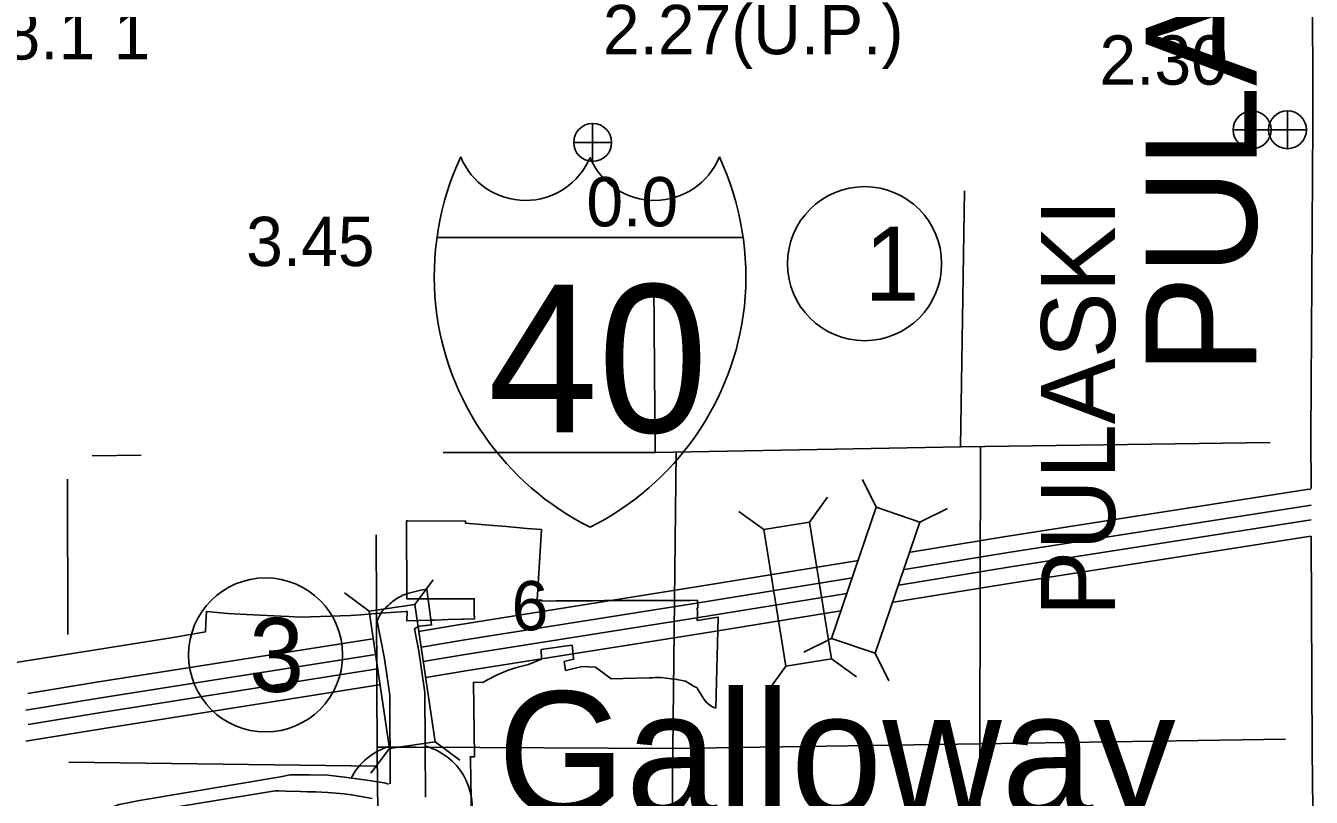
# Model space of a CAD drawing. Extents: x 1127717 to 1741049, y 2026793 to 2244711.
# Drawn here: x 1242222 to 1247728, y 2137280 to 2140586 of the extents above; entities that cross this region are included whole.
import ezdxf

# ---------------------------------------------------------------- set-up
doc = ezdxf.new("R2010")
doc.units = 0
for name, color, linetype in [('10', 7, 'Continuous'), ('15', 7, 'Continuous'), ('19', 7, 'Continuous'), ('2', 7, 'Continuous'), ('20', 7, 'Continuous'), ('23', 7, 'Continuous'), ('24', 7, 'Continuous'), ('25', 7, 'Continuous'), ('26', 7, 'Continuous'), ('27', 7, 'Continuous'), ('30', 7, 'Continuous'), ('4', 7, 'Continuous'), ('5', 7, 'Continuous'), ('58', 7, 'Continuous'), ('6', 7, 'Continuous'), ('Level 30', 7, 'Continuous')]:
    doc.layers.add(name, color=color, linetype=linetype)

msp = doc.modelspace()

# ---------------------------------------------------------------- linework, layer by layer
at = {"layer": '10'}
for points in [[(1243727.1, 2138034.7), (1243730.7, 2138045.4), (1243738.7, 2138060.7), (1243749.6, 2138078.1), (1243759, 2138086.8), (1243764.1, 2138092.6), (1243773.7, 2138101.5), (1243781.3, 2138108.6), (1243786.8, 2138113.3), (1243791.4, 2138117.2), (1243798.7, 2138122.8), (1243806, 2138128), (1243813.3, 2138132.7), (1243821.6, 2138137.6), (1243829.5, 2138141.8), (1243837.4, 2138145.6), (1243845.7, 2138149.1), (1243854.2, 2138152.3), (1243862.8, 2138155.1), (1243914.6, 2138167.8), (1243940.3, 2138171.7), (1243959.9, 2138018.1)], [(1243727.1, 2138034.7), (1243757.5, 2137881.1), (1243767.1, 2137816.1), (1243781.2, 2137717.9)], [(1243886.4, 2138002.3), (1243893.7, 2138006.5), (1243896, 2138007.8), (1243898.4, 2138008.9), (1243900.8, 2138009.9), (1243903.2, 2138010.8), (1243905.7, 2138011.7), (1243908.2, 2138012.4), (1243910.2, 2138012.8), (1243933.1, 2138015.7), (1243936.3, 2138016), (1243959.9, 2138018.1), (1243937.5, 2138016.2), (1243936.7, 2138016.2)], [(1243886.4, 2138002.3), (1243905.4, 2137906.6), (1243915.5, 2137837.7), (1243931.1, 2137729)], [(1243781.2, 2137717.9), (1243783.5, 2137337.7)], [(1243931.1, 2137729), (1243933.8, 2137280.4)]]:
    msp.add_lwpolyline(points, dxfattribs=at)
at = {"layer": '15'}
msp.add_lwpolyline([(1242228.1, 2137005.3), (1242288.1, 2137037.9), (1242295.6, 2137043.4), (1242309.9, 2137054.3), (1242340.9, 2137080.9), (1242411, 2137142.8), (1242436.4, 2137161.8), (1242474, 2137185.2), (1242527.7, 2137209.9), (1242585.3, 2137234.9), (1242622.7, 2137249.3), (1242665.9, 2137258.2), (1242709.8, 2137265.5), (1243312.7, 2137368.1), (1243354.8, 2137376), (1243395.8, 2137376.8), (1243435.9, 2137376.7), (1243515.2, 2137374.8), (1243587.7, 2137366.3), (1243682.5, 2137353), (1243757.1, 2137342.3), (1243777.3, 2137336.7)], dxfattribs=at)
at = {"layer": '19'}
for points in [[(1246011.7, 2138330.4), (1246410.4, 2138395.2), (1247709, 2138598), (1247726.3, 2138600.4)], [(1245985.6, 2138256.5), (1246421.2, 2138327.3), (1247719.1, 2138530), (1247727.6, 2138531.2)], [(1245961.5, 2138189.2), (1246431, 2138265.6), (1247727.6, 2138468.1)], [(1245938.1, 2138115.8), (1246441.8, 2138197.7), (1247726.3, 2138398.3)], [(1244083.4, 2138020.9), (1245084.2, 2138179.6), (1245788.3, 2138294)], [(1244094.2, 2137953), (1245095.1, 2138111.7), (1245762.1, 2138220.1)], [(1244104, 2137891.3), (1245105, 2138050), (1245738.9, 2138153.1)], [(1244114.8, 2137823.4), (1245115.9, 2137982.1), (1245713.5, 2138079.3)], [(1243904.1, 2137990.9), (1244082.6, 2138020.7)], [(1242230.5, 2137724.2), (1242524.5, 2137772.5), (1243708.2, 2137959.4)], [(1243917.2, 2137923.4), (1244094, 2137952.9)], [(1242222.2, 2137653.2), (1242535.4, 2137704.6), (1243719.5, 2137891.5)], [(1243924.5, 2137861.3), (1244104.3, 2137891.3)], [(1242232.3, 2137591.5), (1242545.4, 2137642.9), (1243728, 2137829.6)], [(1243934.9, 2137793.3), (1244115.6, 2137823.5)], [(1242222.5, 2137520.2), (1242556.3, 2137575), (1243735.5, 2137761.2)]]:
    msp.add_lwpolyline(points, dxfattribs=at)
at = {"layer": '2'}
for points in [[(1247663.1, 2144020.7), (1247662.8, 2142760.5), (1247726.6, 2142761.9), (1247731.3, 2141494.2), (1247734.4, 2140166.2), (1247725.8, 2138824.4), (1247726.7, 2138603.6)], [(1247727.6, 2138398.7), (1247731.3, 2137481), (1247745.5, 2136227)]]:
    msp.add_lwpolyline(points, dxfattribs=at)
at = {"layer": '20'}
for p, q in [((1245863.5, 2138522.8), (1245805.2, 2138641.2)), ((1245578, 2138459.4), (1245655.1, 2138566.5)), ((1245382.5, 2138427.7), (1245275.4, 2138504.8)), ((1246051, 2138459.1), (1246169.4, 2138517.4)), ((1243888.6, 2138105.8), (1243967.3, 2138211.7)), ((1243692.7, 2138076.9), (1243586.7, 2138155.6)), ((1243888.6, 2138105.8), (1243692.7, 2138076.9)), ((1243975.2, 2137518.1), (1243888.6, 2138105.8)), ((1243692.7, 2138076.9), (1243779.3, 2137489.3)), ((1245672.4, 2137960.4), (1245554, 2137902)), ((1245673.3, 2137873.1), (1245780.4, 2137796)), ((1245859.9, 2137896.7), (1245918.2, 2137778.3)), ((1245477.9, 2137841.4), (1245400.7, 2137734.3)), ((1243779.3, 2137489.3), (1243700.5, 2137383.3)), ((1243779.3, 2137489.3), (1243975.2, 2137518.1)), ((1243975.2, 2137518.1), (1244081.1, 2137439.4))]:
    msp.add_line(p, q, dxfattribs=at)
for points in [[(1245863.5, 2138522.8), (1245672.4, 2137960.4), (1245859.9, 2137896.7), (1246051, 2138459.1)], [(1245673.3, 2137873.1), (1245578, 2138459.4), (1245382.5, 2138427.7), (1245477.9, 2137841.4)]]:
    msp.add_lwpolyline(points, close=True, dxfattribs=at)
at = {"layer": '23'}
msp.add_line((1243983.5, 2139678.9), (1245294.3, 2139678.9), dxfattribs=at)
for centre, radius, start, end in [((1245201.6, 2139508.1), 1230.1, 155.2204, 185.7928), ((1244362.4, 2140136.7), 299.7, 202.1459, 337.3414), ((1244915.4, 2140136.7), 299.7, 202.6586, 337.8541), ((1244076.1, 2139508.1), 1230.1, 354.2072, 24.7796), ((1245179, 2139518.6), 1208.7, 186.3923, 243.4571), ((1244098.7, 2139518.6), 1208.7, 296.5429, 353.6077)]:
    msp.add_arc(centre, radius, start, end, dxfattribs=at)
at = {"layer": '24'}
for start, end in [(106.5571, 153.0343), (346.4695, 74.2639)]:
    msp.add_arc((1243859.3, 2137235), 275, start, end, dxfattribs=at)
at = {"layer": '26'}
for p, q in [((1247474.3, 2140058.4), (1247474.3, 2140220.9)), ((1247625.8, 2140058.9), (1247625.8, 2140221.4)), ((1244650, 2140004.6), (1244650, 2140167.1)), ((1247393, 2140139.6), (1247555.5, 2140139.6)), ((1247544.6, 2140140.1), (1247707.1, 2140140.1)), ((1244568.8, 2140085.8), (1244731.3, 2140085.8))]:
    msp.add_line(p, q, dxfattribs=at)
for centre in [(1247474.3, 2140139.6), (1247625.8, 2140140.1), (1244650, 2140085.8)]:
    msp.add_circle(centre, 81.2, dxfattribs=at)
at = {"layer": '27'}
for centre in [(1245814.4, 2139566.3), (1243249.3, 2137889.9)]:
    msp.add_circle(centre, 330, dxfattribs=at)
at = {"layer": '4'}
for points in [[(1244916.4, 2138756.8), (1244917.9, 2138756.8), (1246228.8, 2138781), (1247550.9, 2138800.5)], [(1242506.2, 2138743.4), (1242716.9, 2138746)], [(1244916.4, 2138756.8), (1244010.4, 2138757.8)], [(1243747.4, 2134501.7), (1243748.7, 2134801.1), (1243742.4, 2136135.9), (1243727.4, 2137462.4), (1243722.8, 2138403.9)]]:
    msp.add_lwpolyline(points, dxfattribs=at)
at = {"layer": '5'}
for points in [[(1246225.8, 2138780.9), (1246242.2, 2139878.4)], [(1244911.9, 2139470.7), (1244917.7, 2138756.8)], [(1245008.2, 2138758.5), (1244993.1, 2137486.7), (1244981.8, 2136170.8), (1244985.7, 2134830.4), (1244987.2, 2134223.4)], [(1246313.2, 2134435.1), (1246314.3, 2134845.1), (1246309.2, 2136177.5), (1246308.4, 2137514), (1246311.7, 2138782.2)], [(1242401.9, 2137976.9), (1242400.4, 2138642.8)], [(1243892.1, 2137494.4), (1244990, 2137489.6), (1246307.5, 2137509.5), (1247617, 2137529.6)], [(1243892.1, 2137494.4), (1243726.8, 2137494.5)], [(1243726.2, 2137412.6), (1242407.2, 2137430.6)]]:
    msp.add_lwpolyline(points, dxfattribs=at)
at = {"layer": '6'}
for points in [[(1242996, 2138076), (1243087, 2138068), (1243167.9, 2138063.5), (1243315.1, 2138056.5), (1243349.2, 2138054.5), (1243398.5, 2138051.5), (1243612.7, 2138058.5), (1243656.7, 2138061.9), (1243720.4, 2138066.7), (1243849.9, 2138076.6), (1243855.4, 2138077), (1243854.5, 2138035.9), (1243958.2, 2138039), (1243973.1, 2138039.4), (1243973.6, 2138039.4), (1244031.7, 2138041.2), (1244090.6, 2138043), (1244098.9, 2138043.2), (1244144.1, 2138044.6), (1244143.3, 2138054.2), (1244143.1, 2138057.1), (1244142.8, 2138061.3), (1244142.1, 2138070.5), (1244143.1, 2138130.4), (1243853.6, 2138130.9), (1243852.9, 2138463.9), (1243855.3, 2138463.9), (1243856.8, 2138463.9), (1243858.2, 2138463.9), (1244105.5, 2138463.6), (1244105.7, 2138453.9), (1244206.9, 2138445.7), (1244280.7, 2138440.3), (1244367.8, 2138431.7), (1244430.2, 2138427), (1244412.4, 2138124.1), (1244432.6, 2138124), (1244432.5, 2138120.9), (1244491.9, 2138122.1), (1244497.5, 2138122.1), (1244536.9, 2138122.1), (1244595.7, 2138122.2), (1244613.4, 2138122.2), (1244615.2, 2138122.2), (1244616.9, 2138122.2), (1244644.1, 2138122.3), (1244646.4, 2138122.3), (1244648.6, 2138122.3), (1244700.7, 2138122.4), (1244701.9, 2138122.4), (1245044.5, 2138122.8), (1245067.8, 2138123), (1245098.9, 2138123.8), (1245100.1, 2138094.8), (1245100.2, 2138091.9), (1245100.2, 2138091.6), (1245098.2, 2138091.2), (1245098.2, 2138088.7), (1245098.3, 2138074.7), (1245098.3, 2138071.3), (1245098.3, 2138070.9), (1245098.3, 2138067), (1245098.2, 2138036.9), (1245187.5, 2138052.3), (1245176.8, 2137663.1), (1245176.8, 2137661.9), (1245161, 2137669.1), (1245150, 2137675.9), (1245138.5, 2137685.2), (1245127.2, 2137698.6), (1245113.8, 2137721.1), (1245108, 2137731.2), (1245100.8, 2137742.2), (1245098.4, 2137746.8), (1245097.7, 2137748.2), (1245096.7, 2137748.8), (1245091.8, 2137751.5), (1245085.4, 2137755.2), (1245047.1, 2137777.1), (1245003.6, 2137785.4), (1244985.7, 2137787.7), (1244942.9, 2137793.2), (1244942.3, 2137793.3), (1244939.3, 2137793.6), (1244938.3, 2137793.6), (1244918, 2137792.6), (1244905.6, 2137792), (1244893.6, 2137791.4), (1244780.9, 2137789), (1244728.8, 2137787.9), (1244662.4, 2137837.4), (1244604.7, 2137840.4), (1244533.8, 2137823.2), (1244527.5, 2137861.1), (1244568.6, 2137871), (1244568.1, 2137875.3), (1244561.6, 2137932), (1244539.9, 2137928.8), (1244429.3, 2137912.5), (1244430.4, 2137871.3)], [(1242017.4, 2137832.4), (1242861.5, 2137966.1), (1242861.6, 2137966.1), (1242925.6, 2137977), (1242991.8, 2137988.4), (1242993.6, 2138025.8), (1242996, 2138076)], [(1244430.4, 2137871.3), (1244374.8, 2137849.4), (1244329, 2137837.8), (1244288.6, 2137824.6), (1244237.9, 2137802.7), (1244178.9, 2137772.2), (1244140.3, 2137772.5), (1244140.2, 2137772.6), (1244143.7, 2137454.6), (1244143.7, 2137453.3), (1244136.6, 2137453.3), (1244126.1, 2137453.2), (1244126.1, 2137451.4), (1244126.2, 2137447), (1244126.3, 2137443.3), (1244132.2, 2137101.1)], [(1243706.2, 2137274.9), (1243649.9, 2137285.1), (1243616.8, 2137290.2), (1243585.7, 2137294.9), (1243516, 2137301), (1243463.3, 2137302.6), (1243428.1, 2137303.7), (1243398.7, 2137304.6), (1243335.6, 2137306.5), (1243306.3, 2137307.4), (1243290.5, 2137307.9), (1242563.2, 2137189.1)]]:
    msp.add_lwpolyline(points, dxfattribs=at)

# ---------------------------------------------------------------- texts
at = {"layer": '23'}
msp.add_text('40', height=633.6, dxfattribs=at).set_placement((1244201.5, 2138843.3))
at = {"layer": '24'}
msp.add_text('Galloway', height=528, dxfattribs=at).set_placement((1244242.7, 2137205.4))
at = {"layer": '25'}
for s, p in [('2.30', (1246820.6, 2140333.2)), ('0.0', (1244623.3, 2139726))]:
    msp.add_text(s, height=211.2, dxfattribs=at).set_placement(p)
at = {"layer": '27'}
for s, p in [('1', (1245814.4, 2139407.9)), ('3', (1243178.4, 2137731.5))]:
    msp.add_text(s, height=316.8, dxfattribs=at).set_placement(p)
at = {"layer": '30'}
msp.add_text('PULASKI', height=316.8, rotation=90, dxfattribs=at).set_placement((1246887.4, 2138054.3))
at = {"layer": '5'}
msp.add_text('6', height=211.2, dxfattribs=at).set_placement((1244302.9, 2137995.3))
at = {"layer": '58'}
for s, p in [('2.27(U.P.)', (1244693.8, 2140463.6)), ('8.1 1', (1242126.9, 2140441.1)), ('3.45', (1243166.1, 2139556))]:
    msp.add_text(s, height=211.2, dxfattribs=at).set_placement(p)
at = {"layer": 'Level 30'}
msp.add_text('PULASKI  COUNTY', height=475.199, rotation=89.9667, dxfattribs=at).set_placement((1247492.9, 2139091.4))

doc.saveas('drawing.dxf')
